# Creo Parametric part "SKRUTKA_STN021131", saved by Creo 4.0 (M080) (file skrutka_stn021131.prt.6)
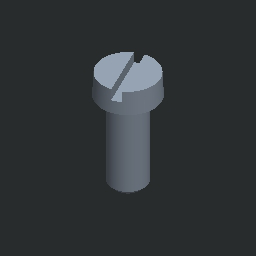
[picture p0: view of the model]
Units: Custom; MM, KILOGRAM, SECS
Materials in the file: OCEL, OCEL_N

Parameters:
  PTC_MATERIAL_NAME = "OCEL"
  NAZOV = "SKRUTKA_STN021131"
  NORMA = "STN 02 1131"

Other parameters: HMOTNOST, HUSTOTA

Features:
  1. chamfer
  2. round
  3. datum plane "DTM2"
  4. datum plane "DTM3"
  5. datum plane "DTM5"

Other named items: BLIND

Layers: 1, 2, 3, 4, 5, 6, 7, 8, 9, 10, 11, 12, 13, 14, 15, 16, 17, 18, 19, 20, 21, 22, 23, 24, 25, 26, 27, 28, 29, 30, 31, 32

Family table entries: GENERIC, SKRUTKA_M1, SKRUTKA_STN021131, value(d_val), value(i_val), SKRUTKA_M1_2, SKRUTKA_STN021131, SKRUTKA_M1_4, SKRUTKA_STN021131, SKRUTKA_M1_6, SKRUTKA_STN021131, SKRUTKA_M2, SKRUTKA_STN021131, SKRUTKA_M2_5, SKRUTKA_STN021131, SKRUTKA_M3, SKRUTKA_STN021131, SKRUTKA_M3_5, SKRUTKA_STN021131, SKRUTKA_M4, SKRUTKA_STN021131, SKRUTKA_M5, SKRUTKA_STN021131, 2/!, SKRUTKA_M6, SKRUTKA_STN021131, 2/$, SKRUTKA_M8, SKRUTKA_STN021131, !/ , 2/*, SKRUTKA_M10, SKRUTKA_STN021131, !/$, 2/0, SKRUTKA_M12, SKRUTKA_STN021131, !/(, 2/2, SKRUTKA_M16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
